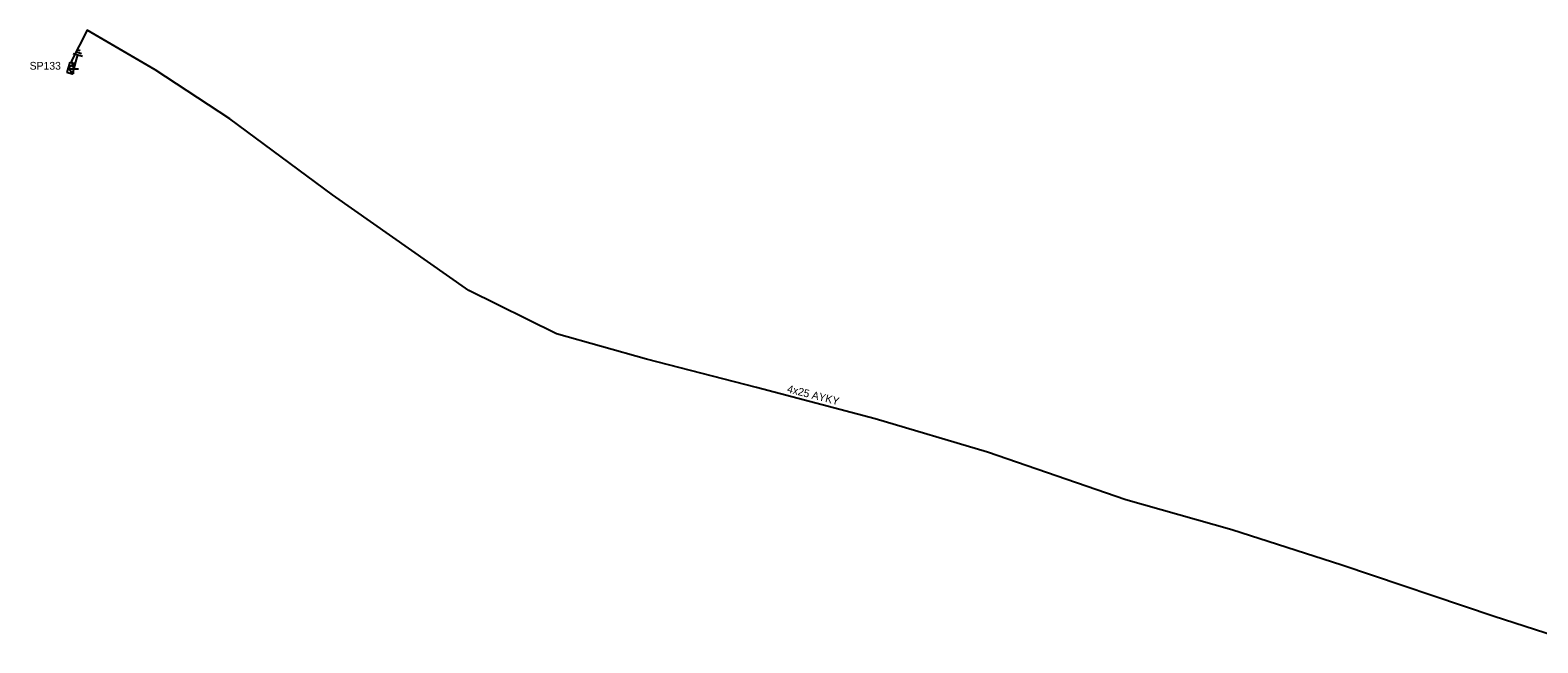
# Model space of a CAD drawing. Extents: x -748492 to -735633, y -1146251 to -1139940.
# Drawn here: x -742492.6 to -742298.6, y -1141000.9 to -1140922 of the extents above; entities that cross this region are included whole.
import ezdxf

# ---------------------------------------------------------------- set-up
doc = ezdxf.new("R2010")
doc.units = 0
for name, color, linetype in [('Vrstva 1', 7, 'Continuous'), ('Vrstva 14', 7, 'Continuous'), ('Vrstva 15', 7, 'Continuous'), ('Vrstva 31', 7, 'Continuous'), ('Vrstva 33', 7, 'Continuous'), ('Vrstva 34', 7, 'Continuous'), ('Vrstva 52', 7, 'Continuous'), ('Vrstva 54', 7, 'Continuous'), ('Vrstva 9', 7, 'Continuous')]:
    doc.layers.add(name, color=color, linetype=linetype)

# ---------------------------------------------------------------- blocks, each defined once
blk = doc.blocks.new('NN800')
at = {"layer": 'Vrstva 1'}
for points in [[(-0.44, 0.44), (0.44, -0.44)], [(-0.44, -0.44), (0.44, 0.44)]]:
    blk.add_lwpolyline(points, dxfattribs=at)
blk = doc.blocks.new('NN630')
at = {"layer": 'Vrstva 9'}
for points in [[(0, -0.7), (-0.7, 0)], [(-0.7, -0.7), (-0.7, 0), (0.7, 0), (0.7, -0.7)], [(-0.7, -0.7), (0.7, -0.7)], [(0, -0.7), (0.7, 0)]]:
    blk.add_lwpolyline(points, dxfattribs=at)
blk = doc.blocks.new('NN810')
at = {"layer": 'Vrstva 14'}
for points in [[(0.63, -1.89), (-0.62, -1.89)], [(0, -0.64), (0, -1.89)], [(0.39, -2.2), (-0.4, -2.2)], [(0, -2.52), (-0.12, -2.52)], [(0.14, -2.52), (0, -2.52)]]:
    blk.add_lwpolyline(points, dxfattribs=at)

msp = doc.modelspace()

# ---------------------------------------------------------------- linework, layer by layer
at = {"layer": 'Vrstva 52'}
msp.add_lwpolyline([(-742291.81, -1140996.66), (-742292.39, -1140996.93), (-742293.74, -1141000.85), (-742304.23, -1140997.47), (-742323.85, -1140990.85), (-742337.97, -1140986.31), (-742351.62, -1140982.43), (-742369.45, -1140976.29), (-742383.88, -1140971.99), (-742399.18, -1140967.99), (-742413.33, -1140964.31), (-742424.91, -1140961.06), (-742436.2, -1140955.47), (-742453.73, -1140943.16), (-742466.96, -1140933.37), (-742476.57, -1140927.08), (-742485.29, -1140921.96), (-742487.33, -1140925.93), (-742487.05, -1140926.95)], dxfattribs=at)

# ---------------------------------------------------------------- block references
at = {"layer": 'Vrstva 15', "rotation": 163.20869717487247}
msp.add_blockref('NN810', (-742487.05, -1140926.95), dxfattribs=at)
at = {"layer": 'Vrstva 31', "rotation": -105.78557966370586}
msp.add_blockref('NN630', (-742487.05, -1140926.95), dxfattribs=at)
at = {"layer": 'Vrstva 34', "rotation": 45}
msp.add_blockref('NN800', (-742487.05, -1140926.95), dxfattribs=at)

# ---------------------------------------------------------------- texts
at = {"layer": 'Vrstva 33'}
msp.add_text('SP133', height=1, rotation=359.992, dxfattribs=at).set_placement((-742492.7, -1140927.05))
at = {"layer": 'Vrstva 54'}
msp.add_text('4x25 AYKY', height=1, rotation=345.795, dxfattribs=at).set_placement((-742395.29, -1140968.58))

doc.saveas('drawing.dxf')
